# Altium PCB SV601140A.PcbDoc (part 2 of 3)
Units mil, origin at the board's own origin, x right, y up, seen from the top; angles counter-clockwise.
Board outline 5208 x 5464 mil, 4 copper layers (Top Layer, MidLayer1, MidLayer2, Bottom Layer), stack 61.2 mil thick; 45 components, 23 nets, 134 pads, 62 vias.
Unrouted connection lines stored in the file: 1.
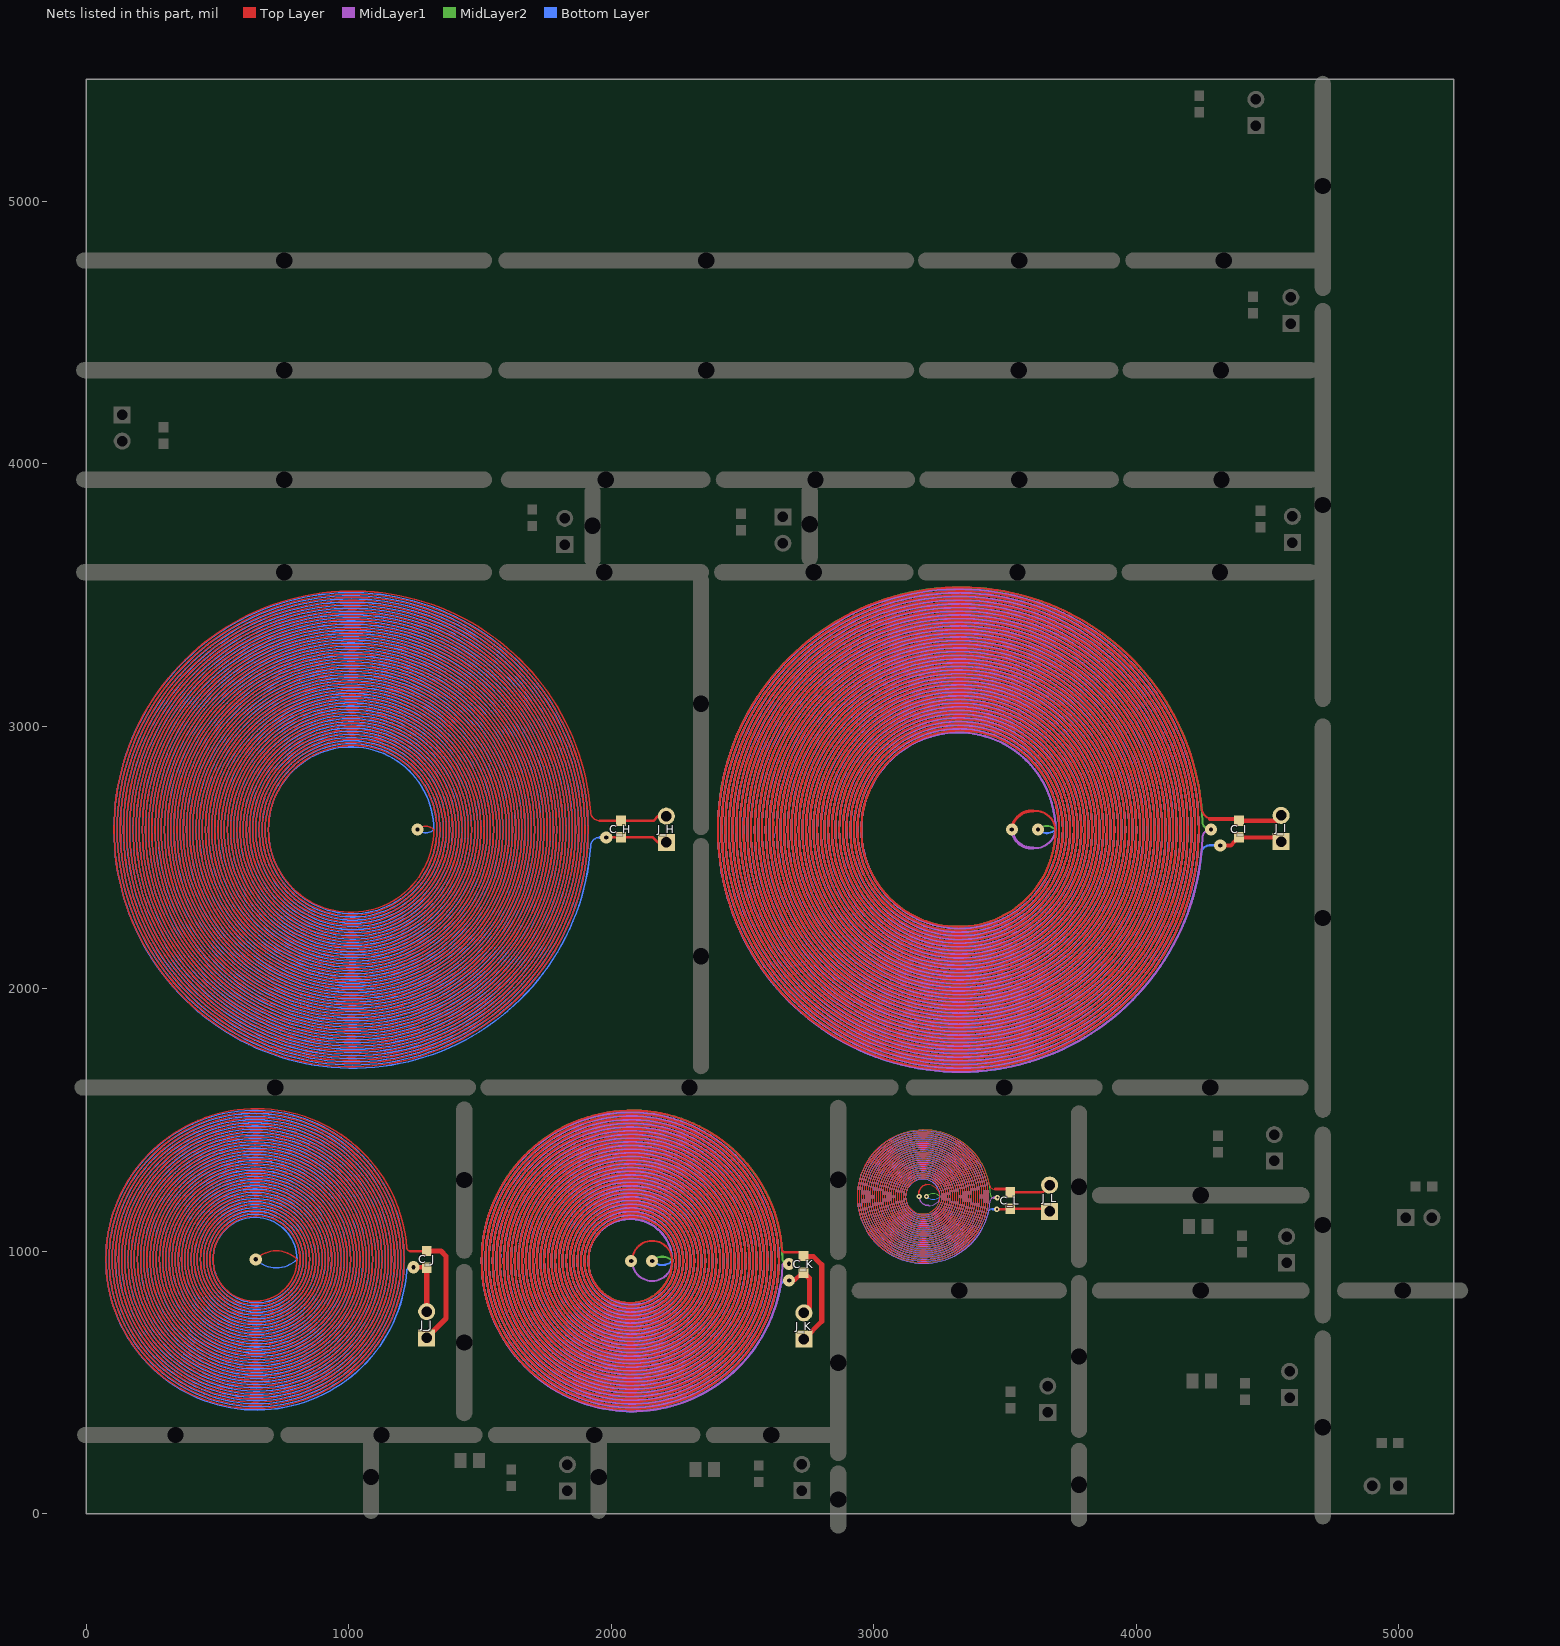
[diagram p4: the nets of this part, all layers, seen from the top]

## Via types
v1: diameter 20, hole 8, Top Layer to Bottom Layer, tented both sides, 49 vias
v2: diameter 46, hole 16, Top Layer to Bottom Layer, tented both sides, 12 vias
v3: diameter 23, hole 8, Top Layer to Bottom Layer, tented both sides, 1 vias

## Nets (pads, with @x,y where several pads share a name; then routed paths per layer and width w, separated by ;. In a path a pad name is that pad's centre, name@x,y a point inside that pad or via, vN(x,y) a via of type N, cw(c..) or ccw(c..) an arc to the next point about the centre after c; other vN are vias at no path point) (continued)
NetC_H_1: C_H.1 C_H.2 J_H.1 J_H.2 | length 385103.4
  Top Layer w6: v2(1261,2606) cw(c1292,2575) 1323,2606 cw(c1008,2606) 693,2606 cw(c1014,2606) 1335,2606 cw(c1008,2606) 681,2606 cw(c1014,2606) 1347,2606 cw(c1008,2606) 669,2606 cw(c1014,2606) 1359,2606 cw(c1008,2606) 657,2606 cw(c1014,2606) 1371,2606 cw(c1008,2606) 645,2606 cw(c1014,2606) 1383,2606 cw(c1008,2606) 633,2606 cw(c1014,2606) 1395,2606 cw(c1008,2606) 621,2606 cw(c1014,2606) 1407,2606 cw(c1008,2606) 609,2606 cw(c1014,2606) 1419,2606 cw(c1008,2606) 597,2606 cw(c1014,2606) 1431,2606 cw(c1008,2606) 585,2606 cw(c1014,2606) 1443,2606 cw(c1008,2606) 573,2606 cw(c1014,2606) 1455,2606 cw(c1008,2606) 561,2606 cw(c1014,2606) 1467,2606 cw(c1008,2606) 549,2606 cw(c1014,2606) 1479,2606 cw(c1008,2606) 537,2606 cw(c1014,2606) 1491,2606 cw(c1008,2606) 525,2606 cw(c1014,2606) 1503,2606 cw(c1008,2606) 513,2606 cw(c1014,2606) 1515,2606 cw(c1008,2606) 501,2606 cw(c1014,2606) 1527,2606 cw(c1008,2606) 489,2606 cw(c1014,2606) 1539,2606 cw(c1008,2606) 477,2606 cw(c1014,2606) 1551,2606 cw(c1008,2606) 465,2606 cw(c1014,2606) 1563,2606 cw(c1008,2606) 453,2606 cw(c1014,2606) 1575,2606 cw(c1008,2606) 441,2606 cw(c1014,2606) 1587,2606 cw(c1008,2606) 429,2606 cw(c1014,2606) 1599,2606 cw(c1008,2606) 417,2606 cw(c1014,2606) 1611,2606 cw(c1008,2606) 405,2606 cw(c1014,2606) 1623,2606 cw(c1008,2606) 393,2606 cw(c1014,2606) 1635,2606 cw(c1008,2606) 381,2606 cw(c1014,2606) 1647,2606 cw(c1008,2606) 369,2606 cw(c1014,2606) 1659,2606 cw(c1008,2606) 357,2606 cw(c1014,2606) 1671,2606 cw(c1008,2606) 345,2606 cw(c1014,2606) 1683,2606 cw(c1008,2606) 333,2606 cw(c1014,2606) 1695,2606 cw(c1008,2606) 321,2606 cw(c1014,2606) 1707,2606 cw(c1008,2606) 309,2606 cw(c1014,2606) 1719,2606 cw(c1008,2606) 297,2606 cw(c1014,2606) 1731,2606 cw(c1008,2606) 285,2606 cw(c1014,2606) 1743,2606 cw(c1008,2606) 273,2606 cw(c1014,2606) 1755,2606 cw(c1008,2606) 261,2606 cw(c1014,2606) 1767,2606 cw(c1008,2606) 249,2606 cw(c1014,2606) 1779,2606 cw(c1008,2606) 237,2606 cw(c1014,2606) 1791,2606 cw(c1008,2606) 225,2606 cw(c1014,2606) 1803,2606 cw(c1008,2606) 213,2606 cw(c1014,2606) 1815,2606 cw(c1008,2606) 201,2606 cw(c1014,2606) 1827,2606 cw(c1008,2606) 189,2606 cw(c1014,2606) 1839,2606 cw(c1008,2606) 177,2606 cw(c1014,2606) 1851,2606 cw(c1008,2606) 165,2606 cw(c1014,2606) 1863,2606 cw(c1008,2606) 153,2606 cw(c1014,2606) 1875,2606 cw(c1008,2606) 141,2606 cw(c1014,2606) 1887,2606 cw(c1008,2606) 129,2606 cw(c1014,2606) 1899,2606 cw(c1008,2606) 117,2606 cw(c1014,2606) 1911,2606 cw(c1008,2606) 105,2606 cw(c1014,2606) 1920.6,2671.97 ccw(c1954.29,2673.68) 1956,2640
  Top Layer w10: 1956,2640 C_H.2@2036,2639.8 2159.5,2639.8 J_H.2@2177,2657.3 ; v2(1980,2576.3) C_H.1@2035.5,2576.3 ; C_H.1@2036,2576.8 2157.5,2576.8 J_H.1@2177,2557.3
  Bottom Layer w6: v2(1261,2606) ccw(c1292,2637) 1323,2606 ccw(c1008,2606) 693,2606 ccw(c1014,2606) 1335,2606 ccw(c1008,2606) 681,2606 ccw(c1014,2606) 1347,2606 ccw(c1008,2606) 669,2606 ccw(c1014,2606) 1359,2606 ccw(c1008,2606) 657,2606 ccw(c1014,2606) 1371,2606 ccw(c1008,2606) 645,2606 ccw(c1014,2606) 1383,2606 ccw(c1008,2606) 633,2606 ccw(c1014,2606) 1395,2606 ccw(c1008,2606) 621,2606 ccw(c1014,2606) 1407,2606 ccw(c1008,2606) 609,2606 ccw(c1014,2606) 1419,2606 ccw(c1008,2606) 597,2606 ccw(c1014,2606) 1431,2606 ccw(c1008,2606) 585,2606 ccw(c1014,2606) 1443,2606 ccw(c1008,2606) 573,2606 ccw(c1014,2606) 1455,2606 ccw(c1008,2606) 561,2606 ccw(c1014,2606) 1467,2606 ccw(c1008,2606) 549,2606 ccw(c1014,2606) 1479,2606 ccw(c1008,2606) 537,2606 ccw(c1014,2606) 1491,2606 ccw(c1008,2606) 525,2606 ccw(c1014,2606) 1503,2606 ccw(c1008,2606) 513,2606 ccw(c1014,2606) 1515,2606 ccw(c1008,2606) 501,2606 ccw(c1014,2606) 1527,2606 ccw(c1008,2606) 489,2606 ccw(c1014,2606) 1539,2606 ccw(c1008,2606) 477,2606 ccw(c1014,2606) 1551,2606 ccw(c1008,2606) 465,2606 ccw(c1014,2606) 1563,2606 ccw(c1008,2606) 453,2606 ccw(c1014,2606) 1575,2606 ccw(c1008,2606) 441,2606 ccw(c1014,2606) 1587,2606 ccw(c1008,2606) 429,2606 ccw(c1014,2606) 1599,2606 ccw(c1008,2606) 417,2606 ccw(c1014,2606) 1611,2606 ccw(c1008,2606) 405,2606 ccw(c1014,2606) 1623,2606 ccw(c1008,2606) 393,2606 ccw(c1014,2606) 1635,2606 ccw(c1008,2606) 381,2606 ccw(c1014,2606) 1647,2606 ccw(c1008,2606) 369,2606 ccw(c1014,2606) 1659,2606 ccw(c1008,2606) 357,2606 ccw(c1014,2606) 1671,2606 ccw(c1008,2606) 345,2606 ccw(c1014,2606) 1683,2606 ccw(c1008,2606) 333,2606 ccw(c1014,2606) 1695,2606 ccw(c1008,2606) 321,2606 ccw(c1014,2606) 1707,2606 ccw(c1008,2606) 309,2606 ccw(c1014,2606) 1719,2606 ccw(c1008,2606) 297,2606 ccw(c1014,2606) 1731,2606 ccw(c1008,2606) 285,2606 ccw(c1014,2606) 1743,2606 ccw(c1008,2606) 273,2606 ccw(c1014,2606) 1755,2606 ccw(c1008,2606) 261,2606 ccw(c1014,2606) 1767,2606 ccw(c1008,2606) 249,2606 ccw(c1014,2606) 1779,2606 ccw(c1008,2606) 237,2606 ccw(c1014,2606) 1791,2606 ccw(c1008,2606) 225,2606 ccw(c1014,2606) 1803,2606 ccw(c1008,2606) 213,2606 ccw(c1014,2606) 1815,2606 ccw(c1008,2606) 201,2606 ccw(c1014,2606) 1827,2606 ccw(c1008,2606) 189,2606 ccw(c1014,2606) 1839,2606 ccw(c1008,2606) 177,2606 ccw(c1014,2606) 1851,2606 ccw(c1008,2606) 165,2606 ccw(c1014,2606) 1863,2606 ccw(c1008,2606) 153,2606 ccw(c1014,2606) 1875,2606 ccw(c1008,2606) 141,2606 ccw(c1014,2606) 1887,2606 ccw(c1008,2606) 129,2606 ccw(c1014,2606) 1899,2606 ccw(c1008,2606) 117,2606 ccw(c1014,2606) 1911,2606 ccw(c1008,2606) 105,2606 ccw(c1014,2606) 1920.85,2543.56 cw(c1954.15,2542.71) 1955,2576
  Bottom Layer w10: 1955,2576 1979.61,2575.91 v2(1980,2576.3)
NetC_I_1: C_I.1 C_I.2 J_I.1 J_I.2 | length 651099.2
  Top Layer w8: 3608,2677 cw(c3614.25,2599.75) 3691.5,2606 cw(c3321.5,2606) 2951.5,2606 cw(c3328.5,2606) 3705.5,2606 cw(c3321.5,2606) 2937.5,2606 cw(c3328.5,2606) 3719.5,2606 cw(c3321.5,2606) 2923.5,2606 cw(c3328.5,2606) 3733.5,2606 cw(c3321.5,2606) 2909.5,2606 cw(c3328.5,2606) 3747.5,2606 cw(c3321.5,2606) 2895.5,2606 cw(c3328.5,2606) 3761.5,2606 cw(c3321.5,2606) 2881.5,2606 cw(c3328.5,2606) 3775.5,2606 cw(c3321.5,2606) 2867.5,2606 cw(c3328.5,2606) 3789.5,2606 cw(c3321.5,2606) 2853.5,2606 cw(c3328.5,2606) 3803.5,2606 cw(c3321.5,2606) 2839.5,2606 cw(c3328.5,2606) 3817.5,2606 cw(c3321.5,2606) 2825.5,2606 cw(c3328.5,2606) 3831.5,2606 cw(c3321.5,2606) 2811.5,2606 cw(c3328.5,2606) 3845.5,2606 cw(c3321.5,2606) 2797.5,2606 cw(c3328.5,2606) 3859.5,2606 cw(c3321.5,2606) 2783.5,2606 cw(c3328.5,2606) 3873.5,2606 cw(c3321.5,2606) 2769.5,2606 cw(c3328.5,2606) 3887.5,2606 cw(c3321.5,2606) 2755.5,2606 cw(c3328.5,2606) 3901.5,2606 cw(c3321.5,2606) 2741.5,2606 cw(c3328.5,2606) 3915.5,2606 cw(c3321.5,2606) 2727.5,2606 cw(c3328.5,2606) 3929.5,2606 cw(c3321.5,2606) 2713.5,2606 cw(c3328.5,2606) 3943.5,2606 cw(c3321.5,2606) 2699.5,2606 cw(c3328.5,2606) 3957.5,2606 cw(c3321.5,2606) 2685.5,2606 cw(c3328.5,2606) 3971.5,2606 cw(c3321.5,2606) 2671.5,2606 cw(c3328.5,2606) 3985.5,2606 cw(c3321.5,2606) 2657.5,2606 cw(c3328.5,2606) 3999.5,2606 cw(c3321.5,2606) 2643.5,2606 cw(c3328.5,2606) 4013.5,2606 cw(c3321.5,2606) 2629.5,2606 cw(c3328.5,2606) 4027.5,2606 cw(c3321.5,2606) 2615.5,2606 cw(c3328.5,2606) 4041.5,2606 cw(c3321.5,2606) 2601.5,2606 cw(c3328.5,2606) 4055.5,2606 cw(c3321.5,2606) 2587.5,2606 cw(c3328.5,2606) 4069.5,2606 cw(c3321.5,2606) 2573.5,2606 cw(c3328.5,2606) 4083.5,2606 cw(c3321.5,2606) 2559.5,2606 cw(c3328.5,2606) 4097.5,2606 cw(c3321.5,2606) 2545.5,2606 cw(c3328.5,2606) 4111.5,2606 cw(c3321.5,2606) 2531.5,2606 cw(c3328.5,2606) 4125.5,2606 cw(c3321.5,2606) 2517.5,2606 cw(c3328.5,2606) 4139.5,2606 cw(c3321.5,2606) 2503.5,2606 cw(c3328.5,2606) 4153.5,2606 cw(c3321.5,2606) 2489.5,2606 cw(c3328.5,2606) 4167.5,2606 cw(c3321.5,2606) 2475.5,2606 cw(c3328.5,2606) 4181.5,2606 cw(c3321.5,2606) 2461.5,2606 cw(c3328.5,2606) 4195.5,2606 cw(c3321.5,2606) 2447.5,2606 cw(c3328.5,2606) 4209.5,2606 cw(c3321.5,2606) 2433.5,2606 cw(c3328.5,2606) 4223.5,2606 cw(c3321.5,2606) 2419.5,2606 cw(c3328.5,2606) 4237.5,2606 cw(c3321.5,2606) 2405.5,2606 cw(c3328.5,2606) 4248.02,2686.09 ccw(c4291.55,2690.53) 4296,2647
  Top Layer w12: v2(3525,2606) cw(c3602,2600) 3608,2677
  Top Layer w16: 4280,2647 C_I.1@4390,2647 ; v2(4319,2546) 4359.5,2546 C_I.2@4373.8,2560.3 ; C_I.2@4390,2576.5 4534.8,2576.5 J_I.1@4551,2560.3 ; C_I.1@4390,2639.5 4530.2,2639.5 J_I.2@4551,2660.3
  MidLayer1 w8: 3608,2536 ccw(c3614.75,2612.75) 3691.5,2606 ccw(c3321.5,2606) 2951.5,2606 ccw(c3328.5,2606) 3705.5,2606 ccw(c3321.5,2606) 2937.5,2606 ccw(c3328.5,2606) 3719.5,2606 ccw(c3321.5,2606) 2923.5,2606 ccw(c3328.5,2606) 3733.5,2606 ccw(c3321.5,2606) 2909.5,2606 ccw(c3328.5,2606) 3747.5,2606 ccw(c3321.5,2606) 2895.5,2606 ccw(c3328.5,2606) 3761.5,2606 ccw(c3321.5,2606) 2881.5,2606 ccw(c3328.5,2606) 3775.5,2606 ccw(c3321.5,2606) 2867.5,2606 ccw(c3328.5,2606) 3789.5,2606 ccw(c3321.5,2606) 2853.5,2606 ccw(c3328.5,2606) 3803.5,2606 ccw(c3321.5,2606) 2839.5,2606 ccw(c3328.5,2606) 3817.5,2606 ccw(c3321.5,2606) 2825.5,2606 ccw(c3328.5,2606) 3831.5,2606 ccw(c3321.5,2606) 2811.5,2606 ccw(c3328.5,2606) 3845.5,2606 ccw(c3321.5,2606) 2797.5,2606 ccw(c3328.5,2606) 3859.5,2606 ccw(c3321.5,2606) 2783.5,2606 ccw(c3328.5,2606) 3873.5,2606 ccw(c3321.5,2606) 2769.5,2606 ccw(c3328.5,2606) 3887.5,2606 ccw(c3321.5,2606) 2755.5,2606 ccw(c3328.5,2606) 3901.5,2606 ccw(c3321.5,2606) 2741.5,2606 ccw(c3328.5,2606) 3915.5,2606 ccw(c3321.5,2606) 2727.5,2606 ccw(c3328.5,2606) 3929.5,2606 ccw(c3321.5,2606) 2713.5,2606 ccw(c3328.5,2606) 3943.5,2606 ccw(c3321.5,2606) 2699.5,2606 ccw(c3328.5,2606) 3957.5,2606 ccw(c3321.5,2606) 2685.5,2606 ccw(c3328.5,2606) 3971.5,2606 ccw(c3321.5,2606) 2671.5,2606 ccw(c3328.5,2606) 3985.5,2606 ccw(c3321.5,2606) 2657.5,2606 ccw(c3328.5,2606) 3999.5,2606 ccw(c3321.5,2606) 2643.5,2606 ccw(c3328.5,2606) 4013.5,2606 ccw(c3321.5,2606) 2629.5,2606 ccw(c3328.5,2606) 4027.5,2606 ccw(c3321.5,2606) 2615.5,2606 ccw(c3328.5,2606) 4041.5,2606 ccw(c3321.5,2606) 2601.5,2606 ccw(c3328.5,2606) 4055.5,2606 ccw(c3321.5,2606) 2587.5,2606 ccw(c3328.5,2606) 4069.5,2606 ccw(c3321.5,2606) 2573.5,2606 ccw(c3328.5,2606) 4083.5,2606 ccw(c3321.5,2606) 2559.5,2606 ccw(c3328.5,2606) 4097.5,2606 ccw(c3321.5,2606) 2545.5,2606 ccw(c3328.5,2606) 4111.5,2606 ccw(c3321.5,2606) 2531.5,2606 ccw(c3328.5,2606) 4125.5,2606 ccw(c3321.5,2606) 2517.5,2606 ccw(c3328.5,2606) 4139.5,2606 ccw(c3321.5,2606) 2503.5,2606 ccw(c3328.5,2606) 4153.5,2606 ccw(c3321.5,2606) 2489.5,2606 ccw(c3328.5,2606) 4167.5,2606 ccw(c3321.5,2606) 2475.5,2606 ccw(c3328.5,2606) 4181.5,2606 ccw(c3321.5,2606) 2461.5,2606 ccw(c3328.5,2606) 4195.5,2606 ccw(c3321.5,2606) 2447.5,2606 ccw(c3328.5,2606) 4209.5,2606 ccw(c3321.5,2606) 2433.5,2606 ccw(c3328.5,2606) 4223.5,2606 ccw(c3321.5,2606) 2419.5,2606 ccw(c3328.5,2606) 4237.5,2606 ccw(c3321.5,2606) 2405.5,2606 ccw(c3328.5,2606) 4250.98,2575.03 cw(c4282.97,2574.01) v2(4284,2606)
  MidLayer1 w12: v2(3525,2606) ccw(c3601.5,2612.5) 3608,2536
  MidLayer2 w8: v2(3625,2606) cw(c3658.25,2572.75) 3691.5,2606 cw(c3321.5,2606) 2951.5,2606 cw(c3328.5,2606) 3705.5,2606 cw(c3321.5,2606) 2937.5,2606 cw(c3328.5,2606) 3719.5,2606 cw(c3321.5,2606) 2923.5,2606 cw(c3328.5,2606) 3733.5,2606 cw(c3321.5,2606) 2909.5,2606 cw(c3328.5,2606) 3747.5,2606 cw(c3321.5,2606) 2895.5,2606 cw(c3328.5,2606) 3761.5,2606 cw(c3321.5,2606) 2881.5,2606 cw(c3328.5,2606) 3775.5,2606 cw(c3321.5,2606) 2867.5,2606 cw(c3328.5,2606) 3789.5,2606 cw(c3321.5,2606) 2853.5,2606 cw(c3328.5,2606) 3803.5,2606 cw(c3321.5,2606) 2839.5,2606 cw(c3328.5,2606) 3817.5,2606 cw(c3321.5,2606) 2825.5,2606 cw(c3328.5,2606) 3831.5,2606 cw(c3321.5,2606) 2811.5,2606 cw(c3328.5,2606) 3845.5,2606 cw(c3321.5,2606) 2797.5,2606 cw(c3328.5,2606) 3859.5,2606 cw(c3321.5,2606) 2783.5,2606 cw(c3328.5,2606) 3873.5,2606 cw(c3321.5,2606) 2769.5,2606 cw(c3328.5,2606) 3887.5,2606 cw(c3321.5,2606) 2755.5,2606 cw(c3328.5,2606) 3901.5,2606 cw(c3321.5,2606) 2741.5,2606 cw(c3328.5,2606) 3915.5,2606 cw(c3321.5,2606) 2727.5,2606 cw(c3328.5,2606) 3929.5,2606 cw(c3321.5,2606) 2713.5,2606 cw(c3328.5,2606) 3943.5,2606 cw(c3321.5,2606) 2699.5,2606 cw(c3328.5,2606) 3957.5,2606 cw(c3321.5,2606) 2685.5,2606 cw(c3328.5,2606) 3971.5,2606 cw(c3321.5,2606) 2671.5,2606 cw(c3328.5,2606) 3985.5,2606 cw(c3321.5,2606) 2657.5,2606 cw(c3328.5,2606) 3999.5,2606 cw(c3321.5,2606) 2643.5,2606 cw(c3328.5,2606) 4013.5,2606 cw(c3321.5,2606) 2629.5,2606 cw(c3328.5,2606) 4027.5,2606 cw(c3321.5,2606) 2615.5,2606 cw(c3328.5,2606) 4041.5,2606 cw(c3321.5,2606) 2601.5,2606 cw(c3328.5,2606) 4055.5,2606 cw(c3321.5,2606) 2587.5,2606 cw(c3328.5,2606) 4069.5,2606 cw(c3321.5,2606) 2573.5,2606 cw(c3328.5,2606) 4083.5,2606 cw(c3321.5,2606) 2559.5,2606 cw(c3328.5,2606) 4097.5,2606 cw(c3321.5,2606) 2545.5,2606 cw(c3328.5,2606) 4111.5,2606 cw(c3321.5,2606) 2531.5,2606 cw(c3328.5,2606) 4125.5,2606 cw(c3321.5,2606) 2517.5,2606 cw(c3328.5,2606) 4139.5,2606 cw(c3321.5,2606) 2503.5,2606 cw(c3328.5,2606) 4153.5,2606 cw(c3321.5,2606) 2489.5,2606 cw(c3328.5,2606) 4167.5,2606 cw(c3321.5,2606) 2475.5,2606 cw(c3328.5,2606) 4181.5,2606 cw(c3321.5,2606) 2461.5,2606 cw(c3328.5,2606) 4195.5,2606 cw(c3321.5,2606) 2447.5,2606 cw(c3328.5,2606) 4209.5,2606 cw(c3321.5,2606) 2433.5,2606 cw(c3328.5,2606) 4223.5,2606 cw(c3321.5,2606) 2419.5,2606 cw(c3328.5,2606) 4237.5,2606 cw(c3321.5,2606) 2405.5,2606 cw(c3328.5,2606) 4251.04,2635.03 ccw(c4282.04,2636.99) v2(4284,2606)
  Bottom Layer w8: v2(3625,2606) ccw(c3658.25,2639.25) 3691.5,2606 ccw(c3321.5,2606) 2951.5,2606 ccw(c3328.5,2606) 3705.5,2606 ccw(c3321.5,2606) 2937.5,2606 ccw(c3328.5,2606) 3719.5,2606 ccw(c3321.5,2606) 2923.5,2606 ccw(c3328.5,2606) 3733.5,2606 ccw(c3321.5,2606) 2909.5,2606 ccw(c3328.5,2606) 3747.5,2606 ccw(c3321.5,2606) 2895.5,2606 ccw(c3328.5,2606) 3761.5,2606 ccw(c3321.5,2606) 2881.5,2606 ccw(c3328.5,2606) 3775.5,2606 ccw(c3321.5,2606) 2867.5,2606 ccw(c3328.5,2606) 3789.5,2606 ccw(c3321.5,2606) 2853.5,2606 ccw(c3328.5,2606) 3803.5,2606 ccw(c3321.5,2606) 2839.5,2606 ccw(c3328.5,2606) 3817.5,2606 ccw(c3321.5,2606) 2825.5,2606 ccw(c3328.5,2606) 3831.5,2606 ccw(c3321.5,2606) 2811.5,2606 ccw(c3328.5,2606) 3845.5,2606 ccw(c3321.5,2606) 2797.5,2606 ccw(c3328.5,2606) 3859.5,2606 ccw(c3321.5,2606) 2783.5,2606 ccw(c3328.5,2606) 3873.5,2606 ccw(c3321.5,2606) 2769.5,2606 ccw(c3328.5,2606) 3887.5,2606 ccw(c3321.5,2606) 2755.5,2606 ccw(c3328.5,2606) 3901.5,2606 ccw(c3321.5,2606) 2741.5,2606 ccw(c3328.5,2606) 3915.5,2606 ccw(c3321.5,2606) 2727.5,2606 ccw(c3328.5,2606) 3929.5,2606 ccw(c3321.5,2606) 2713.5,2606 ccw(c3328.5,2606) 3943.5,2606 ccw(c3321.5,2606) 2699.5,2606 ccw(c3328.5,2606) 3957.5,2606 ccw(c3321.5,2606) 2685.5,2606 ccw(c3328.5,2606) 3971.5,2606 ccw(c3321.5,2606) 2671.5,2606 ccw(c3328.5,2606) 3985.5,2606 ccw(c3321.5,2606) 2657.5,2606 ccw(c3328.5,2606) 3999.5,2606 ccw(c3321.5,2606) 2643.5,2606 ccw(c3328.5,2606) 4013.5,2606 ccw(c3321.5,2606) 2629.5,2606 ccw(c3328.5,2606) 4027.5,2606 ccw(c3321.5,2606) 2615.5,2606 ccw(c3328.5,2606) 4041.5,2606 ccw(c3321.5,2606) 2601.5,2606 ccw(c3328.5,2606) 4055.5,2606 ccw(c3321.5,2606) 2587.5,2606 ccw(c3328.5,2606) 4069.5,2606 ccw(c3321.5,2606) 2573.5,2606 ccw(c3328.5,2606) 4083.5,2606 ccw(c3321.5,2606) 2559.5,2606 ccw(c3328.5,2606) 4097.5,2606 ccw(c3321.5,2606) 2545.5,2606 ccw(c3328.5,2606) 4111.5,2606 ccw(c3321.5,2606) 2531.5,2606 ccw(c3328.5,2606) 4125.5,2606 ccw(c3321.5,2606) 2517.5,2606 ccw(c3328.5,2606) 4139.5,2606 ccw(c3321.5,2606) 2503.5,2606 ccw(c3328.5,2606) 4153.5,2606 ccw(c3321.5,2606) 2489.5,2606 ccw(c3328.5,2606) 4167.5,2606 ccw(c3321.5,2606) 2475.5,2606 ccw(c3328.5,2606) 4181.5,2606 ccw(c3321.5,2606) 2461.5,2606 ccw(c3328.5,2606) 4195.5,2606 ccw(c3321.5,2606) 2447.5,2606 ccw(c3328.5,2606) 4209.5,2606 ccw(c3321.5,2606) 2433.5,2606 ccw(c3328.5,2606) 4223.5,2606 ccw(c3321.5,2606) 2419.5,2606 ccw(c3328.5,2606) 4237.5,2606 ccw(c3321.5,2606) 2405.5,2606 ccw(c3328.5,2606) 4247.07,2515.69 cw(c4278.19,2514.88) 4279,2546
  Bottom Layer w10: 4279,2546 v2(4319,2546)
NetC_J_1: C_J.1 C_J.2 J_J.1 J_J.2 | length 162435.4
  Top Layer w6: v2(645,969) cw(c723.5,890.5) 802,969 cw(c642,969) 482,969 cw(c648,969) 814,969 cw(c642,969) 470,969 cw(c648,969) 826,969 cw(c642,969) 458,969 cw(c648,969) 838,969 cw(c642,969) 446,969 cw(c648,969) 850,969 cw(c642,969) 434,969 cw(c648,969) 862,969 cw(c642,969) 422,969 cw(c648,969) 874,969 cw(c642,969) 410,969 cw(c648,969) 886,969 cw(c642,969) 398,969 cw(c648,969) 898,969 cw(c642,969) 386,969 cw(c648,969) 910,969 cw(c642,969) 374,969 cw(c648,969) 922,969 cw(c642,969) 362,969 cw(c648,969) 934,969 cw(c642,969) 350,969 cw(c648,969) 946,969 cw(c642,969) 338,969 cw(c648,969) 958,969 cw(c642,969) 326,969 cw(c648,969) 970,969 cw(c642,969) 314,969 cw(c648,969) 982,969 cw(c642,969) 302,969 cw(c648,969) 994,969 cw(c642,969) 290,969 cw(c648,969) 1006,969 cw(c642,969) 278,969 cw(c648,969) 1018,969 cw(c642,969) 266,969 cw(c648,969) 1030,969 cw(c642,969) 254,969 cw(c648,969) 1042,969 cw(c642,969) 242,969 cw(c648,969) 1054,969 cw(c642,969) 230,969 cw(c648,969) 1066,969 cw(c642,969) 218,969 cw(c648,969) 1078,969 cw(c642,969) 206,969 cw(c648,969) 1090,969 cw(c642,969) 194,969 cw(c648,969) 1102,969 cw(c642,969) 182,969 cw(c648,969) 1114,969 cw(c642,969) 170,969 cw(c648,969) 1126,969 cw(c642,969) 158,969 cw(c648,969) 1138,969 cw(c642,969) 146,969 cw(c648,969) 1150,969 cw(c642,969) 134,969 cw(c648,969) 1162,969 cw(c642,969) 122,969 cw(c648,969) 1174,969 cw(c642,969) 110,969 cw(c648,969) 1186,969 cw(c642,969) 98,969 cw(c648,969) 1198,969 cw(c642,969) 86,969 cw(c648,969) 1210,969 cw(c642,969) 74,969 cw(c648,969) 1220.3,1013.18 ccw(c1233.24,1013.44) 1233.5,1000.5
  Top Layer w10: 1233.5,1000.5 C_J.2@1296,1000.5 ; C_J.1@1294.5,939 C_J.1@1296,937.5
  Top Layer w16: v2(1246,939) C_J.1@1294.5,939
  Top Layer w20: J_J.1@1296,670 1370,744 1370,981 1350.5,1000.5 C_J.2@1296,1000.5 ; J_J.2@1296,770 C_J.1@1296,937.5
  Bottom Layer w6: v2(645,969) ccw(c723.5,1047.5) 802,969 ccw(c642,969) 482,969 ccw(c648,969) 814,969 ccw(c642,969) 470,969 ccw(c648,969) 826,969 ccw(c642,969) 458,969 ccw(c648,969) 838,969 ccw(c642,969) 446,969 ccw(c648,969) 850,969 ccw(c642,969) 434,969 ccw(c648,969) 862,969 ccw(c642,969) 422,969 ccw(c648,969) 874,969 ccw(c642,969) 410,969 ccw(c648,969) 886,969 ccw(c642,969) 398,969 ccw(c648,969) 898,969 ccw(c642,969) 386,969 ccw(c648,969) 910,969 ccw(c642,969) 374,969 ccw(c648,969) 922,969 ccw(c642,969) 362,969 ccw(c648,969) 934,969 ccw(c642,969) 350,969 ccw(c648,969) 946,969 ccw(c642,969) 338,969 ccw(c648,969) 958,969 ccw(c642,969) 326,969 ccw(c648,969) 970,969 ccw(c642,969) 314,969 ccw(c648,969) 982,969 ccw(c642,969) 302,969 ccw(c648,969) 994,969 ccw(c642,969) 290,969 ccw(c648,969) 1006,969 ccw(c642,969) 278,969 ccw(c648,969) 1018,969 ccw(c642,969) 266,969 ccw(c648,969) 1030,969 ccw(c642,969) 254,969 ccw(c648,969) 1042,969 ccw(c642,969) 242,969 ccw(c648,969) 1054,969 ccw(c642,969) 230,969 ccw(c648,969) 1066,969 ccw(c642,969) 218,969 ccw(c648,969) 1078,969 ccw(c642,969) 206,969 ccw(c648,969) 1090,969 ccw(c642,969) 194,969 ccw(c648,969) 1102,969 ccw(c642,969) 182,969 ccw(c648,969) 1114,969 ccw(c642,969) 170,969 ccw(c648,969) 1126,969 ccw(c642,969) 158,969 ccw(c648,969) 1138,969 ccw(c642,969) 146,969 ccw(c648,969) 1150,969 ccw(c642,969) 134,969 ccw(c648,969) 1162,969 ccw(c642,969) 122,969 ccw(c648,969) 1174,969 ccw(c642,969) 110,969 ccw(c648,969) 1186,969 ccw(c642,969) 98,969 ccw(c648,969) 1198,969 ccw(c642,969) 86,969 ccw(c648,969) 1210,969 ccw(c642,969) 74,969 ccw(c648,969) 1220.4,926.12 cw(c1233.14,926.26) v2@1233,939
  Bottom Layer w10: v2@1232,939 v2(1246,939)
NetC_K_1: C_K.1 C_K.2 J_K.1 J_K.2 | length 277644.5
  Top Layer w8: v2@2078.5,963 cw(c2155,963) 2231.5,963 cw(c2071.5,963) 1911.5,963 cw(c2078.5,963) 2245.5,963 cw(c2071.5,963) 1897.5,963 cw(c2078.5,963) 2259.5,963 cw(c2071.5,963) 1883.5,963 cw(c2078.5,963) 2273.5,963 cw(c2071.5,963) 1869.5,963 cw(c2078.5,963) 2287.5,963 cw(c2071.5,963) 1855.5,963 cw(c2078.5,963) 2301.5,963 cw(c2071.5,963) 1841.5,963 cw(c2078.5,963) 2315.5,963 cw(c2071.5,963) 1827.5,963 cw(c2078.5,963) 2329.5,963 cw(c2071.5,963) 1813.5,963 cw(c2078.5,963) 2343.5,963 cw(c2071.5,963) 1799.5,963 cw(c2078.5,963) 2357.5,963 cw(c2071.5,963) 1785.5,963 cw(c2078.5,963) 2371.5,963 cw(c2071.5,963) 1771.5,963 cw(c2078.5,963) 2385.5,963 cw(c2071.5,963) 1757.5,963 cw(c2078.5,963) 2399.5,963 cw(c2071.5,963) 1743.5,963 cw(c2078.5,963) 2413.5,963 cw(c2071.5,963) 1729.5,963 cw(c2078.5,963) 2427.5,963 cw(c2071.5,963) 1715.5,963 cw(c2078.5,963) 2441.5,963 cw(c2071.5,963) 1701.5,963 cw(c2078.5,963) 2455.5,963 cw(c2071.5,963) 1687.5,963 cw(c2078.5,963) 2469.5,963 cw(c2071.5,963) 1673.5,963 cw(c2078.5,963) 2483.5,963 cw(c2071.5,963) 1659.5,963 cw(c2078.5,963) 2497.5,963 cw(c2071.5,963) 1645.5,963 cw(c2078.5,963) 2511.5,963 cw(c2071.5,963) 1631.5,963 cw(c2078.5,963) 2525.5,963 cw(c2071.5,963) 1617.5,963 cw(c2078.5,963) 2539.5,963 cw(c2071.5,963) 1603.5,963 cw(c2078.5,963) 2553.5,963 cw(c2071.5,963) 1589.5,963 cw(c2078.5,963) 2567.5,963 cw(c2071.5,963) 1575.5,963 cw(c2078.5,963) 2581.5,963 cw(c2071.5,963) 1561.5,963 cw(c2078.5,963) 2595.5,963 cw(c2071.5,963) 1547.5,963 cw(c2078.5,963) 2609.5,963 cw(c2071.5,963) 1533.5,963 cw(c2078.5,963) 2623.5,963 cw(c2071.5,963) 1519.5,963 cw(c2078.5,963) 2637.5,963 cw(c2071.5,963) 1505.5,963 cw(c2078.5,963) 2650.1,1003.08 ccw(c2658.09,1003.99) 2659,996
  Top Layer w10: 2659,996 C_K.2@2727.5,996
  Top Layer w16: v2(2677,888) 2696.5,888 C_K.1@2727,918.5
  Top Layer w20: C_K.2@2727,981.5 2729.5,979 2770,979 2801,948 2801,733 J_K.1@2733,665 ; C_K.1@2732,918.5 2754,896.5 2754,786 J_K.2@2733,765
  MidLayer1 w8: v2@2078.5,963 ccw(c2155,963) 2231.5,963 ccw(c2071.5,963) 1911.5,963 ccw(c2078.5,963) 2245.5,963 ccw(c2071.5,963) 1897.5,963 ccw(c2078.5,963) 2259.5,963 ccw(c2071.5,963) 1883.5,963 ccw(c2078.5,963) 2273.5,963 ccw(c2071.5,963) 1869.5,963 ccw(c2078.5,963) 2287.5,963 ccw(c2071.5,963) 1855.5,963 ccw(c2078.5,963) 2301.5,963 ccw(c2071.5,963) 1841.5,963 ccw(c2078.5,963) 2315.5,963 ccw(c2071.5,963) 1827.5,963 ccw(c2078.5,963) 2329.5,963 ccw(c2071.5,963) 1813.5,963 ccw(c2078.5,963) 2343.5,963 ccw(c2071.5,963) 1799.5,963 ccw(c2078.5,963) 2357.5,963 ccw(c2071.5,963) 1785.5,963 ccw(c2078.5,963) 2371.5,963 ccw(c2071.5,963) 1771.5,963 ccw(c2078.5,963) 2385.5,963 ccw(c2071.5,963) 1757.5,963 ccw(c2078.5,963) 2399.5,963 ccw(c2071.5,963) 1743.5,963 ccw(c2078.5,963) 2413.5,963 ccw(c2071.5,963) 1729.5,963 ccw(c2078.5,963) 2427.5,963 ccw(c2071.5,963) 1715.5,963 ccw(c2078.5,963) 2441.5,963 ccw(c2071.5,963) 1701.5,963 ccw(c2078.5,963) 2455.5,963 ccw(c2071.5,963) 1687.5,963 ccw(c2078.5,963) 2469.5,963 ccw(c2071.5,963) 1673.5,963 ccw(c2078.5,963) 2483.5,963 ccw(c2071.5,963) 1659.5,963 ccw(c2078.5,963) 2497.5,963 ccw(c2071.5,963) 1645.5,963 ccw(c2078.5,963) 2511.5,963 ccw(c2071.5,963) 1631.5,963 ccw(c2078.5,963) 2525.5,963 ccw(c2071.5,963) 1617.5,963 ccw(c2078.5,963) 2539.5,963 ccw(c2071.5,963) 1603.5,963 ccw(c2078.5,963) 2553.5,963 ccw(c2071.5,963) 1589.5,963 ccw(c2078.5,963) 2567.5,963 ccw(c2071.5,963) 1575.5,963 ccw(c2078.5,963) 2581.5,963 ccw(c2071.5,963) 1561.5,963 ccw(c2078.5,963) 2595.5,963 ccw(c2071.5,963) 1547.5,963 ccw(c2078.5,963) 2609.5,963 ccw(c2071.5,963) 1533.5,963 ccw(c2078.5,963) 2623.5,963 ccw(c2071.5,963) 1519.5,963 ccw(c2078.5,963) 2637.5,963 ccw(c2071.5,963) 1505.5,963 ccw(c2078.5,963) 2651.15,942.99 cw(c2659.08,944.07) v2@2658,952
  MidLayer1 w10: v2@2658,952 v2(2676,952)
  MidLayer2 w8: v2(2155,963) cw(c2193.25,924.75) 2231.5,963 cw(c2071.5,963) 1911.5,963 cw(c2078.5,963) 2245.5,963 cw(c2071.5,963) 1897.5,963 cw(c2078.5,963) 2259.5,963 cw(c2071.5,963) 1883.5,963 cw(c2078.5,963) 2273.5,963 cw(c2071.5,963) 1869.5,963 cw(c2078.5,963) 2287.5,963 cw(c2071.5,963) 1855.5,963 cw(c2078.5,963) 2301.5,963 cw(c2071.5,963) 1841.5,963 cw(c2078.5,963) 2315.5,963 cw(c2071.5,963) 1827.5,963 cw(c2078.5,963) 2329.5,963 cw(c2071.5,963) 1813.5,963 cw(c2078.5,963) 2343.5,963 cw(c2071.5,963) 1799.5,963 cw(c2078.5,963) 2357.5,963 cw(c2071.5,963) 1785.5,963 cw(c2078.5,963) 2371.5,963 cw(c2071.5,963) 1771.5,963 cw(c2078.5,963) 2385.5,963 cw(c2071.5,963) 1757.5,963 cw(c2078.5,963) 2399.5,963 cw(c2071.5,963) 1743.5,963 cw(c2078.5,963) 2413.5,963 cw(c2071.5,963) 1729.5,963 cw(c2078.5,963) 2427.5,963 cw(c2071.5,963) 1715.5,963 cw(c2078.5,963) 2441.5,963 cw(c2071.5,963) 1701.5,963 cw(c2078.5,963) 2455.5,963 cw(c2071.5,963) 1687.5,963 cw(c2078.5,963) 2469.5,963 cw(c2071.5,963) 1673.5,963 cw(c2078.5,963) 2483.5,963 cw(c2071.5,963) 1659.5,963 cw(c2078.5,963) 2497.5,963 cw(c2071.5,963) 1645.5,963 cw(c2078.5,963) 2511.5,963 cw(c2071.5,963) 1631.5,963 cw(c2078.5,963) 2525.5,963 cw(c2071.5,963) 1617.5,963 cw(c2078.5,963) 2539.5,963 cw(c2071.5,963) 1603.5,963 cw(c2078.5,963) 2553.5,963 cw(c2071.5,963) 1589.5,963 cw(c2078.5,963) 2567.5,963 cw(c2071.5,963) 1575.5,963 cw(c2078.5,963) 2581.5,963 cw(c2071.5,963) 1561.5,963 cw(c2078.5,963) 2595.5,963 cw(c2071.5,963) 1547.5,963 cw(c2078.5,963) 2609.5,963 cw(c2071.5,963) 1533.5,963 cw(c2078.5,963) 2623.5,963 cw(c2071.5,963) 1519.5,963 cw(c2078.5,963) 2637.5,963 cw(c2071.5,963) 1505.5,963 cw(c2078.5,963) 2651.44,970.99 ccw(c2673.22,973.77) v2(2676,952)
  Bottom Layer w8: v2(2155,963) ccw(c2193.25,1001.25) 2231.5,963 ccw(c2071.5,963) 1911.5,963 ccw(c2078.5,963) 2245.5,963 ccw(c2071.5,963) 1897.5,963 ccw(c2078.5,963) 2259.5,963 ccw(c2071.5,963) 1883.5,963 ccw(c2078.5,963) 2273.5,963 ccw(c2071.5,963) 1869.5,963 ccw(c2078.5,963) 2287.5,963 ccw(c2071.5,963) 1855.5,963 ccw(c2078.5,963) 2301.5,963 ccw(c2071.5,963) 1841.5,963 ccw(c2078.5,963) 2315.5,963 ccw(c2071.5,963) 1827.5,963 ccw(c2078.5,963) 2329.5,963 ccw(c2071.5,963) 1813.5,963 ccw(c2078.5,963) 2343.5,963 ccw(c2071.5,963) 1799.5,963 ccw(c2078.5,963) 2357.5,963 ccw(c2071.5,963) 1785.5,963 ccw(c2078.5,963) 2371.5,963 ccw(c2071.5,963) 1771.5,963 ccw(c2078.5,963) 2385.5,963 ccw(c2071.5,963) 1757.5,963 ccw(c2078.5,963) 2399.5,963 ccw(c2071.5,963) 1743.5,963 ccw(c2078.5,963) 2413.5,963 ccw(c2071.5,963) 1729.5,963 ccw(c2078.5,963) 2427.5,963 ccw(c2071.5,963) 1715.5,963 ccw(c2078.5,963) 2441.5,963 ccw(c2071.5,963) 1701.5,963 ccw(c2078.5,963) 2455.5,963 ccw(c2071.5,963) 1687.5,963 ccw(c2078.5,963) 2469.5,963 ccw(c2071.5,963) 1673.5,963 ccw(c2078.5,963) 2483.5,963 ccw(c2071.5,963) 1659.5,963 ccw(c2078.5,963) 2497.5,963 ccw(c2071.5,963) 1645.5,963 ccw(c2078.5,963) 2511.5,963 ccw(c2071.5,963) 1631.5,963 ccw(c2078.5,963) 2525.5,963 ccw(c2071.5,963) 1617.5,963 ccw(c2078.5,963) 2539.5,963 ccw(c2071.5,963) 1603.5,963 ccw(c2078.5,963) 2553.5,963 ccw(c2071.5,963) 1589.5,963 ccw(c2078.5,963) 2567.5,963 ccw(c2071.5,963) 1575.5,963 ccw(c2078.5,963) 2581.5,963 ccw(c2071.5,963) 1561.5,963 ccw(c2078.5,963) 2595.5,963 ccw(c2071.5,963) 1547.5,963 ccw(c2078.5,963) 2609.5,963 ccw(c2071.5,963) 1533.5,963 ccw(c2078.5,963) 2623.5,963 ccw(c2071.5,963) 1519.5,963 ccw(c2078.5,963) 2637.5,963 ccw(c2071.5,963) 1505.5,963 ccw(c2078.5,963) 2643.88,869.87 cw(c2669.51,862.37) v2(2677,888)
  other v2: 2075,963
NetC_L_1: C_L.1 C_L.2 J_L.1 J_L.2 | length 97295.3
  Top Layer w4: 3198,1254 cw(c3202,1204) 3252,1208 cw(c3186,1208) 3120,1208 cw(c3190,1208) 3260,1208 cw(c3186,1208) 3112,1208 cw(c3190,1208) 3268,1208 cw(c3186,1208) 3104,1208 cw(c3190,1208) 3276,1208 cw(c3186,1208) 3096,1208 cw(c3190,1208) 3284,1208 cw(c3186,1208) 3088,1208 cw(c3190,1208) 3292,1208 cw(c3186,1208) 3080,1208 cw(c3190,1208) 3300,1208 cw(c3186,1208) 3072,1208 cw(c3190,1208) 3308,1208 cw(c3186,1208) 3064,1208 cw(c3190,1208) 3316,1208 cw(c3186,1208) 3056,1208 cw(c3190,1208) 3324,1208 cw(c3186,1208) 3048,1208 cw(c3190,1208) 3332,1208 cw(c3186,1208) 3040,1208 cw(c3190,1208) 3340,1208 cw(c3186,1208) 3032,1208 cw(c3190,1208) 3348,1208 cw(c3186,1208) 3024,1208 cw(c3190,1208) 3356,1208 cw(c3186,1208) 3016,1208 cw(c3190,1208) 3364,1208 cw(c3186,1208) 3008,1208 cw(c3190,1208) 3372,1208 cw(c3186,1208) 3000,1208 cw(c3190,1208) 3380,1208 cw(c3186,1208) 2992,1208 cw(c3190,1208) 3388,1208 cw(c3186,1208) 2984,1208 cw(c3190,1208) 3396,1208 cw(c3186,1208) 2976,1208 cw(c3190,1208) 3404,1208 cw(c3186,1208) 2968,1208 cw(c3190,1208) 3412,1208 cw(c3186,1208) 2960,1208 cw(c3190,1208) 3420,1208 cw(c3186,1208) 2952,1208 cw(c3190,1208) 3428,1208 cw(c3186,1208) 2944,1208 cw(c3190,1208) 3436,1208 cw(c3186,1208) 2936,1208 cw(c3190,1208) 3440.16,1252.03 ccw(c3458.59,1255.44) 3462,1237
  Top Layer w6: v1(3172,1208) cw(c3208,1218) 3198,1254
  Top Layer w10: 3462,1237 C_L.2@3506.5,1237 ; v1(3468,1160) C_L.1@3517.5,1160 ; C_L.1@3519,1161.5 3659.5,1161.5 J_L.1@3669,1152 ; C_L.2@3519,1224.5 3641.5,1224.5 J_L.2@3669,1252
  MidLayer1 w4: 3208,1174 ccw(c3213,1213) 3252,1208 ccw(c3186,1208) 3120,1208 ccw(c3190,1208) 3260,1208 ccw(c3186,1208) 3112,1208 ccw(c3190,1208) 3268,1208 ccw(c3186,1208) 3104,1208 ccw(c3190,1208) 3276,1208 ccw(c3186,1208) 3096,1208 ccw(c3190,1208) 3284,1208 ccw(c3186,1208) 3088,1208 ccw(c3190,1208) 3292,1208 ccw(c3186,1208) 3080,1208 ccw(c3190,1208) 3300,1208 ccw(c3186,1208) 3072,1208 ccw(c3190,1208) 3308,1208 ccw(c3186,1208) 3064,1208 ccw(c3190,1208) 3316,1208 ccw(c3186,1208) 3056,1208 ccw(c3190,1208) 3324,1208 ccw(c3186,1208) 3048,1208 ccw(c3190,1208) 3332,1208 ccw(c3186,1208) 3040,1208 ccw(c3190,1208) 3340,1208 ccw(c3186,1208) 3032,1208 ccw(c3190,1208) 3348,1208 ccw(c3186,1208) 3024,1208 ccw(c3190,1208) 3356,1208 ccw(c3186,1208) 3016,1208 ccw(c3190,1208) 3364,1208 ccw(c3186,1208) 3008,1208 ccw(c3190,1208) 3372,1208 ccw(c3186,1208) 3000,1208 ccw(c3190,1208) 3380,1208 ccw(c3186,1208) 2992,1208 ccw(c3190,1208) 3388,1208 ccw(c3186,1208) 2984,1208 ccw(c3190,1208) 3396,1208 ccw(c3186,1208) 2976,1208 ccw(c3190,1208) 3404,1208 ccw(c3186,1208) 2968,1208 ccw(c3190,1208) 3412,1208 ccw(c3186,1208) 2960,1208 ccw(c3190,1208) 3420,1208 ccw(c3186,1208) 2952,1208 ccw(c3190,1208) 3428,1208 ccw(c3186,1208) 2944,1208 ccw(c3190,1208) 3436,1208 ccw(c3186,1208) 2936,1208 ccw(c3190,1208) 3443.56,1193.03 cw(c3455.27,1192.29) 3456,1204
  MidLayer1 w6: v1(3172,1208) ccw(c3207,1209) 3208,1174
  MidLayer1 w10: 3456,1204 v1(3470,1204)
  MidLayer2 w4: v1(3200,1208) cw(c3226,1182) 3252,1208 cw(c3186,1208) 3120,1208 cw(c3190,1208) 3260,1208 cw(c3186,1208) 3112,1208 cw(c3190,1208) 3268,1208 cw(c3186,1208) 3104,1208 cw(c3190,1208) 3276,1208 cw(c3186,1208) 3096,1208 cw(c3190,1208) 3284,1208 cw(c3186,1208) 3088,1208 cw(c3190,1208) 3292,1208 cw(c3186,1208) 3080,1208 cw(c3190,1208) 3300,1208 cw(c3186,1208) 3072,1208 cw(c3190,1208) 3308,1208 cw(c3186,1208) 3064,1208 cw(c3190,1208) 3316,1208 cw(c3186,1208) 3056,1208 cw(c3190,1208) 3324,1208 cw(c3186,1208) 3048,1208 cw(c3190,1208) 3332,1208 cw(c3186,1208) 3040,1208 cw(c3190,1208) 3340,1208 cw(c3186,1208) 3032,1208 cw(c3190,1208) 3348,1208 cw(c3186,1208) 3024,1208 cw(c3190,1208) 3356,1208 cw(c3186,1208) 3016,1208 cw(c3190,1208) 3364,1208 cw(c3186,1208) 3008,1208 cw(c3190,1208) 3372,1208 cw(c3186,1208) 3000,1208 cw(c3190,1208) 3380,1208 cw(c3186,1208) 2992,1208 cw(c3190,1208) 3388,1208 cw(c3186,1208) 2984,1208 cw(c3190,1208) 3396,1208 cw(c3186,1208) 2976,1208 cw(c3190,1208) 3404,1208 cw(c3186,1208) 2968,1208 cw(c3190,1208) 3412,1208 cw(c3186,1208) 2960,1208 cw(c3190,1208) 3420,1208 cw(c3186,1208) 2952,1208 cw(c3190,1208) 3428,1208 cw(c3186,1208) 2944,1208 cw(c3190,1208) 3436,1208 cw(c3186,1208) 2936,1208 cw(c3190,1208) 3443.95,1213 ccw(c3454.47,1214.52) 3456,1204
  MidLayer2 w10: 3456,1204 v1(3470,1204)
  Bottom Layer w4: v1(3200,1208) ccw(c3226,1234) 3252,1208 ccw(c3186,1208) 3120,1208 ccw(c3190,1208) 3260,1208 ccw(c3186,1208) 3112,1208 ccw(c3190,1208) 3268,1208 ccw(c3186,1208) 3104,1208 ccw(c3190,1208) 3276,1208 ccw(c3186,1208) 3096,1208 ccw(c3190,1208) 3284,1208 ccw(c3186,1208) 3088,1208 ccw(c3190,1208) 3292,1208 ccw(c3186,1208) 3080,1208 ccw(c3190,1208) 3300,1208 ccw(c3186,1208) 3072,1208 ccw(c3190,1208) 3308,1208 ccw(c3186,1208) 3064,1208 ccw(c3190,1208) 3316,1208 ccw(c3186,1208) 3056,1208 ccw(c3190,1208) 3324,1208 ccw(c3186,1208) 3048,1208 ccw(c3190,1208) 3332,1208 ccw(c3186,1208) 3040,1208 ccw(c3190,1208) 3340,1208 ccw(c3186,1208) 3032,1208 ccw(c3190,1208) 3348,1208 ccw(c3186,1208) 3024,1208 ccw(c3190,1208) 3356,1208 ccw(c3186,1208) 3016,1208 ccw(c3190,1208) 3364,1208 ccw(c3186,1208) 3008,1208 ccw(c3190,1208) 3372,1208 ccw(c3186,1208) 3000,1208 ccw(c3190,1208) 3380,1208 ccw(c3186,1208) 2992,1208 ccw(c3190,1208) 3388,1208 ccw(c3186,1208) 2984,1208 ccw(c3190,1208) 3396,1208 ccw(c3186,1208) 2976,1208 ccw(c3190,1208) 3404,1208 ccw(c3186,1208) 2968,1208 ccw(c3190,1208) 3412,1208 ccw(c3186,1208) 2960,1208 ccw(c3190,1208) 3420,1208 ccw(c3186,1208) 2952,1208 ccw(c3190,1208) 3428,1208 ccw(c3186,1208) 2944,1208 ccw(c3190,1208) 3436,1208 ccw(c3186,1208) 2936,1208 ccw(c3190,1208) 3438.07,1153.43 cw(c3448.82,1149.25) 3453,1160
  Bottom Layer w10: 3453,1160 v1(3468,1160)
